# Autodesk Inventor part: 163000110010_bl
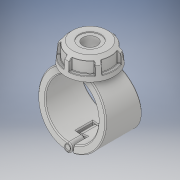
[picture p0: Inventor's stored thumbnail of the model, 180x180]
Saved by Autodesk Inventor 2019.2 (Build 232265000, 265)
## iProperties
Created: 2022-02
Part Number: 163000110010_bl
Material: Generic
Description: Plassadle Threaded 110x1''
Document SubType Name: Modeling
Designer: comp2
Density: 1 g/cm^3
Appearance: Default
Author: comp2
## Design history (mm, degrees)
derived "16300.ipt"
feature "Solid1::16300.ipt" dims "ScaleForDerivedMember" = 10
feature "Solid2::16300.ipt" dims "ScaleForDerivedMember" = 10
feature "Solid3::16300.ipt" dims "ScaleForDerivedMember" = 10
feature "Solid4::16300.ipt" dims "ScaleForDerivedMember" = 10
tag "TaggingFeature1"
body "Solid1"
body "Solid2"
body "Solid3"
body "Solid4"
other parameters: "d2" = 141 [user parameter], "d3" = 55 [user parameter], "d7" = 133.95 [user parameter], "d8" = 85 deg [user parameter], "d9" = 45 deg [user parameter], "d10" = 102 [user parameter], "d11" = 49 [user parameter], "d12" = 27.7935 [user parameter], "d13" = 42.84 [user parameter], "d14" = 45.4365 [user parameter], "d42" = 3.1 [user parameter], "d49" = 2.82 [user parameter], "d50" = 97 [user parameter], "d51" = 0 [user parameter], "d52" = 21.7 [user parameter], "d53" = 77.55 [user parameter], "d54" = 33.95 [user parameter], "d55" = 0 [user parameter], "d56" = 19.4 [user parameter], "d57" = 19.4 [user parameter], "d59" = 0 [user parameter], "d60" = 97 [user parameter], "d61" = 0 [user parameter], "d62" = 33.95 [user parameter], "d63" = 0 [user parameter], "d65" = 0 [user parameter], "d67" = 0 [user parameter], "d69" = 0 [user parameter], "d70" = 1 [user parameter], "d71" = 93.12 [user parameter], "d72" = 0 [user parameter], "d73" = 2 [user parameter], "d78" = 86.7 [user parameter], "d79" = 5.1 [user parameter], "d80" = 60 deg [user parameter], "d81" = 5.1 [user parameter], "d84" = 0 [user parameter], "d85" = 1 [user parameter], "d87" = 360 deg [user parameter], "d122" = 49 [user parameter], "d124" = 42.80128 [user parameter], "d125" = 1.98525 [user parameter], "d129" = 30.291 [user parameter], "d130" = 25.74735 [user parameter], "d131" = 31.85 [user parameter], "d132" = 45 deg [user parameter], "d133" = 22.295 [user parameter], "d134" = 15.1455 [user parameter], "d136" = 0 [user parameter], "d138" = 0 [user parameter], "d1" = 25 [user parameter], "B" = 141 [user parameter], "L" = 97 [user parameter], "E_" = 54 [user parameter], "E1" = 102 [user parameter], "H2" = 49 [user parameter], "H3" = 78 [user parameter], "H_costum" = 49 [user parameter], "Rp" = 30.291 [user parameter], "d128" = 39.705 [user parameter]
